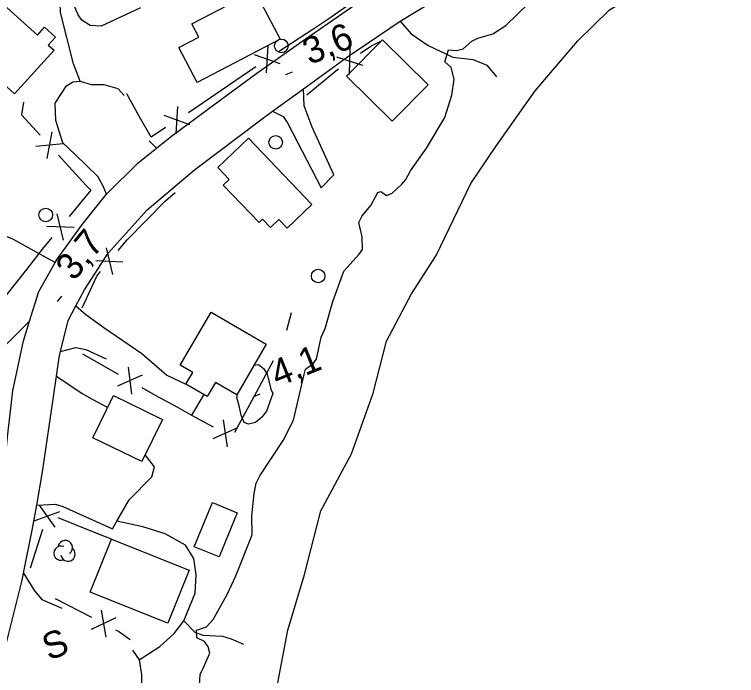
# Model space of a CAD drawing. Extents: x 362852 to 366875, y 5563573 to 5566479.
# Drawn here: x 363645.6 to 363751.9, y 5564327.8 to 5564425 of the extents above; entities that cross this region are included whole.
import ezdxf

# ---------------------------------------------------------------- set-up
doc = ezdxf.new("R2010")
doc.units = 0
for name, color, linetype in [('Niveau 19', 7, 'Continuous'), ('Niveau 2', 7, 'Continuous'), ('Niveau 21', 7, 'Continuous'), ('Niveau 22', 7, 'Continuous'), ('Niveau 3', 7, 'Continuous'), ('Niveau 31', 7, 'Continuous'), ('Niveau 36', 7, 'Continuous'), ('Niveau 37', 7, 'Continuous'), ('Niveau 4', 7, 'Continuous'), ('Niveau 44', 7, 'Continuous'), ('Niveau 52', 7, 'Continuous')]:
    doc.layers.add(name, color=color, linetype=linetype)

msp = doc.modelspace()

# ---------------------------------------------------------------- linework, layer by layer
at = {"layer": 'Niveau 19'}
for p, q in [((363665.45, 5564406.44), (363666.53, 5564405.35)), ((363673.49, 5564369.1), (363671.69, 5564366.1))]:
    msp.add_line(p, q, dxfattribs=at)
for points in [[(363659.15, 5564398.59), (363658.69, 5564399.76), (363657.87, 5564401.17), (363654.56, 5564404.42), (363652.75, 5564406.15), (363651.73, 5564409.44), (363651.63, 5564411.98), (363653.29, 5564414.51), (363654.23, 5564415.09), (363655.28, 5564415.21), (363656.89, 5564414.74), (363658.76, 5564414.7), (363660.85, 5564414.13), (363661.79, 5564413.08)], [(363683.61, 5564410.8), (363685.17, 5564410.03), (363685.87, 5564408.98), (363690.75, 5564399.52), (363692.62, 5564401.42), (363689.45, 5564408.43), (363688.27, 5564411.58), (363688.13, 5564414.08)], [(363654.68, 5564382.16), (363656.13, 5564380.87), (363658.78, 5564378.96), (363664.38, 5564375.14), (363668.06, 5564371.95), (363670.86, 5564370.63)], [(363647.85, 5564379.9), (363644.08, 5564376.12), (363635.38, 5564368.96), (363633.34, 5564367.42), (363635.98, 5564364.71), (363639.54, 5564367.39), (363640.76, 5564367.47), (363642.75, 5564365.26), (363644.67, 5564363.3)], [(363652.42, 5564375.45), (363654.65, 5564376.05), (363656.15, 5564375.74), (363659.13, 5564374.38)], [(363651.8, 5564371.81), (363655.59, 5564369.28), (363657.04, 5564368.43), (363659.36, 5564367.23)], [(363648.9, 5564352.83), (363651.68, 5564353.01), (363652.72, 5564352.63), (363660.03, 5564349.38), (363660.69, 5564350.5), (363662.52, 5564353.63), (363665.82, 5564356.99), (363666.23, 5564358.46), (363664.84, 5564360.25)]]:
    msp.add_lwpolyline(points, dxfattribs=at)
at = {"layer": 'Niveau 2'}
for points in [[(363708.92, 5564418.05), (363709.5, 5564419.8), (363710.66, 5564419.72), (363711.64, 5564419.94), (363712.9, 5564421.1), (363713.79, 5564421.54), (363716.03, 5564422.17), (363717.9, 5564423.39), (363721.24, 5564426.61), (363724.2, 5564430.61), (363728.15, 5564433.59), (363732.18, 5564436.22), (363735.39, 5564439.33), (363738.28, 5564442.74), (363740.07, 5564444.3), (363741.48, 5564444.52), (363742.39, 5564445.03), (363743.59, 5564446.35), (363747.18, 5564449.3), (363750.3, 5564452.17), (363754.8, 5564454.88)], [(363664.18, 5564426.01), (363658.36, 5564423.31), (363656.76, 5564423.39), (363655.55, 5564424.2), (363654.98, 5564424.96), (363654.51, 5564426.08)], [(363672.75, 5564324.68), (363672.94, 5564327.95), (363673.37, 5564328.88), (363674.39, 5564331.07), (363674.12, 5564332.02), (363673.6, 5564332.81), (363672.44, 5564333.32), (363672.41, 5564334.44), (363673.9, 5564334.94), (363674.88, 5564336.04), (363676.9, 5564339.71), (363678.2, 5564342.45), (363680.62, 5564348.48), (363680.57, 5564351.28), (363680.89, 5564354.55), (363681.19, 5564356.06), (363681.73, 5564357.16), (363685.18, 5564362.37), (363686.7, 5564365.33), (363688.26, 5564372.07), (363688.44, 5564372.83), (363689.58, 5564373.69), (363690.06, 5564374.33), (363690.77, 5564377.57), (363691.32, 5564378.81), (363692.46, 5564382.8), (363694.1, 5564387.25), (363696.36, 5564389.77), (363696.82, 5564390.46), (363696.79, 5564392.33), (363696.28, 5564394.43), (363696.76, 5564395.39), (363698.05, 5564396.93), (363699.08, 5564398.81), (363699.51, 5564398.99), (363700.38, 5564398.41), (363701.18, 5564398.75), (363702.63, 5564400.05), (363703.22, 5564400.74), (363703.88, 5564402.01), (363706.24, 5564405.33), (363708.92, 5564409.84), (363709.97, 5564413.16), (363710.31, 5564415.5), (363709.9, 5564417.21), (363708.92, 5564418.05)], [(363680.87, 5564373.42), (363681.53, 5564373.52), (363682.27, 5564372.95), (363682.8, 5564372.12), (363683.36, 5564369.91), (363683.63, 5564369.27)], [(363683.63, 5564369.27), (363682.71, 5564366.69), (363682.03, 5564365.78), (363681.1, 5564365.01), (363680.07, 5564364.77), (363679.41, 5564365), (363678.97, 5564366.06), (363678.7, 5564367.45), (363678.36, 5564368.69), (363678.44, 5564369.24)]]:
    msp.add_lwpolyline(points, dxfattribs=at)
at = {"layer": 'Niveau 21'}
for points in [[(363637.3, 5564325.71), (363639.69, 5564337.17), (363642.51, 5564348.52), (363643.91, 5564355.92), (363644.67, 5564363.3), (363645.37, 5564369.67), (363646.94, 5564376.99), (363647.85, 5564379.9), (363649.21, 5564384.27), (363651.61, 5564388.52), (363651.9, 5564389.03), (363655.63, 5564394.16), (363659.15, 5564398.59), (363663.85, 5564403.19), (363666.53, 5564405.35), (363668.71, 5564407.11), (363675.16, 5564411.89), (363681.3, 5564416.36), (363688.42, 5564421.37), (363695.85, 5564426.51)], [(363640.79, 5564317.62), (363643.9, 5564330.42), (363646.74, 5564341.82), (363646.95, 5564342.83), (363648.25, 5564349.17), (363648.9, 5564352.83), (363649.77, 5564357.76), (363650.96, 5564366.09), (363651.8, 5564371.81), (363652.2, 5564374.55), (363652.42, 5564375.45), (363653.54, 5564380), (363654.68, 5564382.16), (363655.91, 5564384.5), (363659.41, 5564389.93), (363665.13, 5564396.28), (363672.12, 5564402.17), (363682.05, 5564409.67), (363683.61, 5564410.8), (363688.13, 5564414.08), (363694.63, 5564418.77), (363702.37, 5564424.02), (363706.58, 5564426.58)]]:
    msp.add_lwpolyline(points, dxfattribs=at)
at = {"layer": 'Niveau 22'}
for points in [[(363655.28, 5564415.21), (363654.29, 5564417.77), (363652.38, 5564425.29), (363652.32, 5564428.24), (363652.92, 5564429.76), (363654.93, 5564431.71), (363658.43, 5564434.39), (363660.6, 5564436.77), (363663.68, 5564438.88), (363665.15, 5564439.93), (363667.82, 5564443.16), (363669.59, 5564445.31), (363673, 5564450.55), (363674.85, 5564453.89), (363675.21, 5564456.54), (363675.27, 5564457.22), (363675.42, 5564459.16), (363675.32, 5564460.75), (363675.07, 5564462.33), (363674.27, 5564464.07)], [(363702.37, 5564424.02), (363704, 5564422.15), (363706.48, 5564420.45), (363710.13, 5564418.76), (363713.12, 5564418.4), (363715.11, 5564417.56), (363716.53, 5564415.83)], [(363651.61, 5564388.52), (363649.46, 5564389.72), (363645.48, 5564391.93), (363638.21, 5564395), (363631.48, 5564397.52), (363624.57, 5564400.21)], [(363663.98, 5564330.09), (363667.03, 5564332.03), (363669.1, 5564333.99), (363670.57, 5564335.81), (363672.22, 5564339.92), (363672.34, 5564342.58), (363672.02, 5564344.98), (363670.77, 5564346.96), (363667.8, 5564348.63), (363664.52, 5564349.65), (363660.69, 5564350.5)], [(363670.57, 5564335.81), (363672.16, 5564334.14), (363673.33, 5564333.72), (363676.25, 5564333.55), (363677.53, 5564333.17), (363679.31, 5564332.4)]]:
    msp.add_lwpolyline(points, dxfattribs=at)
at = {"layer": 'Niveau 3'}
for p, q in [((363685.53, 5564416.19), (363686.51, 5564416.58)), ((363651.96, 5564382.79), (363652.62, 5564383.59)), ((363680.82, 5564368.81), (363681.78, 5564369.2))]:
    msp.add_line(p, q, dxfattribs=at)
at = {"layer": 'Niveau 31'}
for points in [[(363671.74, 5564423.64), (363680.99, 5564428.49), (363684.72, 5564421.4), (363672.53, 5564415), (363669.83, 5564420.14), (363672.77, 5564421.68), (363671.74, 5564423.64)], [(363650.6, 5564420.52), (363651.46, 5564419.75), (363645.64, 5564413.32), (363636.79, 5564421.32), (363637.31, 5564421.89), (363635.43, 5564423.6), (363638.09, 5564426.55), (363639.91, 5564424.89), (363642.56, 5564427.82), (363649.01, 5564421.98), (363650.06, 5564423.14), (363651.66, 5564421.69), (363650.6, 5564420.52)], [(363706.51, 5564414.69), (363701.21, 5564409.3), (363694.47, 5564415.92), (363699.77, 5564421.31), (363706.51, 5564414.69)], [(363681.61, 5564394.4), (363676.32, 5564399.92), (363677.2, 5564400.76), (363675.54, 5564402.5), (363680.06, 5564406.82), (363689.38, 5564397.09), (363685.73, 5564393.59), (363684.51, 5564394.86), (363683.29, 5564393.69), (363682.13, 5564394.9), (363681.61, 5564394.4)], [(363674.57, 5564381.25), (363682.68, 5564376.53), (363678.34, 5564369.08), (363675.2, 5564370.9), (363673.99, 5564368.81), (363670.86, 5564370.63), (363671.87, 5564372.37), (363670.02, 5564373.45), (363674.57, 5564381.25)], [(363660.21, 5564368.97), (363667.39, 5564365.46), (363664.36, 5564359.26), (363657.18, 5564362.77), (363660.21, 5564368.97)], [(363675.74, 5564345.23), (363672.09, 5564346.72), (363674.74, 5564353.21), (363678.4, 5564351.71), (363675.74, 5564345.23)], [(363659.91, 5564347.86), (363671.33, 5564343.29), (363668.2, 5564335.47), (363656.78, 5564340.04), (363659.91, 5564347.86)]]:
    msp.add_lwpolyline(points, dxfattribs=at)
at = {"layer": 'Niveau 36'}
for centre in [(363684.9, 5564420.39), (363684.06, 5564406.21), (363650.23, 5564395.53), (363690.31, 5564386.54)]:
    msp.add_circle(centre, 1, dxfattribs=at)
at = {"layer": 'Niveau 37'}
for p, q in [((363689.5, 5564422.81), (363684.48, 5564419.51)), ((363682.69, 5564416.42), (363682.94, 5564420.42)), ((363694.99, 5564420.17), (363694.86, 5564416.17)), ((363684.7, 5564417.74), (363680.93, 5564419.1)), ((363693.02, 5564418.79), (363696.82, 5564417.55)), ((363681.15, 5564417.3), (363676.19, 5564413.92)), ((363664.04, 5564409.97), (363662.14, 5564413.35)), ((363669.41, 5564407.48), (363669.68, 5564411.48)), ((363671.42, 5564408.8), (363667.67, 5564410.16)), ((363651.14, 5564407.74), (363650.41, 5564403.81)), ((363652.77, 5564405.97), (363648.78, 5564405.58)), ((363652.13, 5564404.3), (363656.19, 5564399.88)), ((363652.86, 5564391.81), (363651.92, 5564395.7)), ((363654.39, 5564393.66), (363650.4, 5564393.85)), ((363659.13, 5564390.68), (363660.05, 5564386.79)), ((363657.59, 5564388.84), (363661.59, 5564388.63)), ((363685.68, 5564378.6), (363686.38, 5564381.19)), ((363655.66, 5564375.09), (363660.88, 5564372.13)), ((363680.9, 5564368.84), (363683.74, 5564374.12)), ((363662.36, 5564373.12), (363662.86, 5564369.15)), ((363664.44, 5564371.94), (363660.78, 5564370.34)), ((363678.05, 5564363.56), (363680.9, 5564368.84)), ((363676.33, 5564365.38), (363676.9, 5564361.43)), ((363678.44, 5564364.23), (363674.8, 5564362.58)), ((363649.24, 5564352.85), (363651.57, 5564349.6)), ((363648.52, 5564350.56), (363652.29, 5564351.89)), ((363652.01, 5564351.02), (363657.58, 5564348.79)), ((363648, 5564343.6), (363649.8, 5564349.32)), ((363657.58, 5564348.79), (363660.1, 5564347.79)), ((363651.63, 5564339.12), (363656.95, 5564336.35)), ((363658.4, 5564337.4), (363659.05, 5564333.45)), ((363660.53, 5564336.29), (363656.92, 5564334.56))]:
    msp.add_line(p, q, dxfattribs=at)
for points in [[(363694.47, 5564426.17), (363691.71, 5564424.27), (363689.5, 5564422.81)], [(363696.56, 5564419.32), (363698.06, 5564420.37), (363699.55, 5564421.09)], [(363688.66, 5564413.21), (363692.89, 5564416.75), (363693.29, 5564417.03)], [(363676.19, 5564413.92), (363672.74, 5564411.56), (363671.22, 5564410.57)], [(363646.96, 5564412.14), (363646.65, 5564410.27), (363649.43, 5564407.25)], [(363667.87, 5564408.38), (363665.72, 5564406.98), (363664.04, 5564409.97)], [(363656.19, 5564399.88), (363656.86, 5564399.16), (363653.67, 5564395.29)], [(363664.95, 5564394.67), (363667.84, 5564397.61), (363669.26, 5564398.84)], [(363660.87, 5564390.28), (363662.21, 5564391.88), (363664.95, 5564394.67)], [(363651.12, 5564392.21), (363649.71, 5564390.5), (363647.38, 5564387.52)], [(363647.38, 5564387.52), (363644.36, 5564383.67), (363643.29, 5564383.37)], [(363655.58, 5564381.89), (363657.73, 5564386.51), (363658.31, 5564387.2)], [(363664.36, 5564370.15), (363666.33, 5564369.03), (363669.6, 5564367.24)], [(363669.6, 5564367.24), (363671.69, 5564366.1), (363674.87, 5564364.36)], [(363660.5, 5564334.51), (363660.92, 5564334.29), (363662.63, 5564333.07)]]:
    msp.add_lwpolyline(points, dxfattribs=at)
at = {"layer": 'Niveau 4'}
msp.add_lwpolyline([(363684.16, 5564325.69), (363685.87, 5564334.46), (363688.28, 5564342.63), (363690.69, 5564351.99), (363695.19, 5564360.41), (363698.42, 5564369.31), (363700.35, 5564376.97), (363704.03, 5564383.91), (363707.69, 5564389.54), (363712.77, 5564400.15), (363716.45, 5564405.59), (363722.24, 5564413.8), (363728.5, 5564421.14), (363733.19, 5564425.69), (363735.84, 5564427.3), (363737.24, 5564428.58), (363738.1, 5564429.69), (363739.28, 5564431.51), (363743.57, 5564435.2), (363751.5, 5564440.67), (363755.53, 5564443.18)], dxfattribs=at)
at = {"layer": 'Niveau 44'}
for centre, start, end in [((363652.48, 5564345.78), 66.2054, 291.894), ((363653.11, 5564346.6), 304.3592, 171.8163), ((363653.51, 5564345.63), 189.0269, 51.7112)]:
    msp.add_arc(centre, 1.05, start, end, dxfattribs=at)
at = {"layer": 'Niveau 52'}
for points in [[(363646.95, 5564342.83), (363648.56, 5564340.25), (363649.66, 5564338.96), (363652.61, 5564337.68)], [(363663.01, 5564331.5), (363663.98, 5564330.09), (363664.33, 5564327.92), (363664.25, 5564323.81), (363664.23, 5564322.93), (363664.22, 5564319.8), (363664.22, 5564319.23), (363663.42, 5564317.19), (363662.23, 5564316.31), (363660.9, 5564316.5), (363661.33, 5564318.44), (363659.95, 5564321.51), (363659.91, 5564321.57)]]:
    msp.add_lwpolyline(points, dxfattribs=at)

# ---------------------------------------------------------------- texts
at = {"layer": 'Niveau 3'}
for s, rotation, p in [('3,6  ', 22.09, (363689.05, 5564417.56)), ('3,7  ', 50.6894, (363654.39, 5564385.66)), ('4,1  ', 22.09, (363684.33, 5564370.17))]:
    msp.add_text(s, height=3.93, rotation=rotation, dxfattribs=at).set_placement(p)
at = {"layer": 'Niveau 52'}
msp.add_text('S', height=3.93, rotation=22.09, dxfattribs=at).set_placement((363650.71, 5564329.92))

doc.saveas('drawing.dxf')
